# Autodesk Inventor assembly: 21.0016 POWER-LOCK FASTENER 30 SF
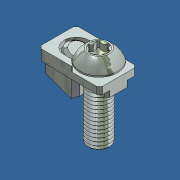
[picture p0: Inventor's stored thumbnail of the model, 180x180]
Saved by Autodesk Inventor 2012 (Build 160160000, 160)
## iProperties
Created: 2015-06
Part Number: 21.0016 POWER-LOCK FASTENER 30 SF
Document SubType Name: Assembly
Designer: Admin
Author: Admin
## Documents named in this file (4)
- C:\Andys Backup Data\ANDY'S INVENTOR\INVENTOR LIBRARIES\PARTS LIBRARY\30 SERIES\21.0016 POWER-LOCK FASTENER 30 SF.iam
- C:\Andys Backup Data\ANDY'S INVENTOR\INVENTOR LIBRARIES\PARTS LIBRARY\30 SERIES\SUBCOMPONENTS\21.0016 POWER-LOCK 30 BODY.ipt
- C:\Andys Backup Data\ANDY'S INVENTOR\INVENTOR LIBRARIES\PARTS LIBRARY\FASTENING ELEMENTS\SUBCOMPONENTS\21.1492 POWER-LOCK SF TORX SCREW.ipt
- C:\Andys Backup Data\ANDY'S INVENTOR\INVENTOR LIBRARIES\PARTS LIBRARY\FASTENING ELEMENTS\SET SCREWS\M8X12 SET SCREW FLAT POINT.ipt
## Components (3 placed, 3 different names)
1. 21.0016 POWER-LOCK 30 BODY:1 — Mate:2, Angle:2, Mate:3, Angle:3, Mate:4
2. 21.1492 POWER-LOCK SF TORX SCREW:1 — Mate:2, Angle:2, Mate:3, Mate:5
3. M8X12 SET SCREW FLAT POINT:1 — Angle:3, Mate:4, Mate:5
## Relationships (6: Mate 4, Angle 2)
- Mate:2: 21.0016 POWER-LOCK 30 BODY:1 ↔ 21.1492 POWER-LOCK SF TORX SCREW:1
- Angle:2: 21.0016 POWER-LOCK 30 BODY:1 ↔ 21.1492 POWER-LOCK SF TORX SCREW:1
- Mate:3: 21.0016 POWER-LOCK 30 BODY:1 ↔ 21.1492 POWER-LOCK SF TORX SCREW:1
- Angle:3: 21.0016 POWER-LOCK 30 BODY:1 ↔ M8X12 SET SCREW FLAT POINT:1
- Mate:4: 21.0016 POWER-LOCK 30 BODY:1 ↔ M8X12 SET SCREW FLAT POINT:1
- Mate:5: 21.1492 POWER-LOCK SF TORX SCREW:1 ↔ M8X12 SET SCREW FLAT POINT:1
